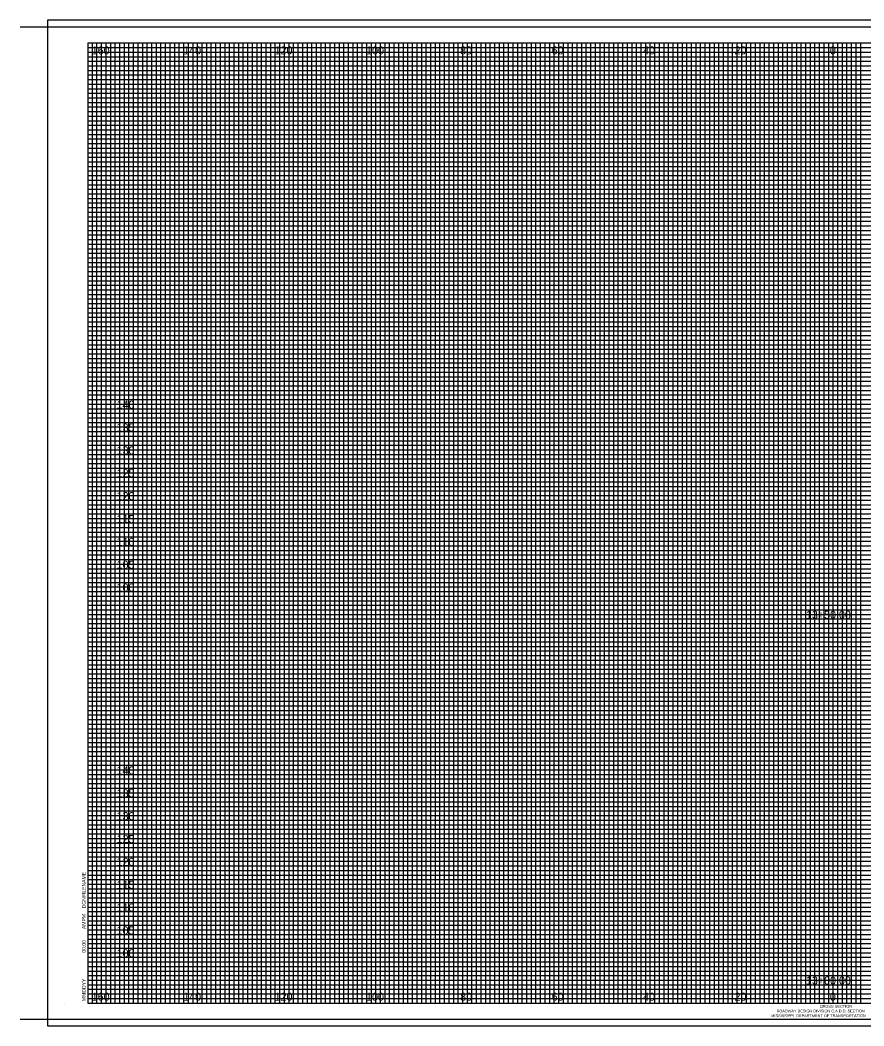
# Model space of a CAD drawing. Extents: x 21281 to 21817, y 6470 to 8300.
# Drawn here: x 21465 to 21649.5, y 7159.8 to 7379.8 of the extents above; entities that cross this region are included whole.
import ezdxf

# ---------------------------------------------------------------- set-up
doc = ezdxf.new("R2010")
doc.units = 0
for name, color, linetype in [('SHEET_BORDER', 7, 'Continuous'), ('SHEET_BORDER_TX', 7, 'Continuous'), ('SHEET_DATE_DGN_TX', 7, 'Continuous'), ('SHEET_PLOTTING_SHAPE', 7, 'Continuous'), ('XS_SHEET_LABELS_ELEVATION', 7, 'Continuous'), ('XS_SHEET_LABELS_OFFSET', 7, 'Continuous'), ('XS_SHEET_LABELS_STATION', 7, 'Continuous'), ('XS_SHEET_MAJOR_GRIDS', 7, 'Continuous'), ('XS_SHEET_MEDIUM_GRIDS', 7, 'Continuous'), ('XS_SHEET_MINOR_GRIDS', 7, 'Continuous')]:
    doc.layers.add(name, color=color, linetype=linetype)

msp = doc.modelspace()

# ---------------------------------------------------------------- linework, layer by layer
at = {"layer": 'SHEET_BORDER'}
for p, q in [((21465.04, 7378.34), (21817.04, 7378.34)), ((21479.84, 7374.84), (21814.84, 7374.84)), ((21479.84, 7374.84), (21479.84, 7164.84)), ((21623.84, 7164.84), (21623.84, 7374.84)), ((21474.84, 7164.84), (21474.84, 7164.84)), ((21479.84, 7164.84), (21814.84, 7164.84)), ((21465.04, 7161.34), (21817.04, 7161.34))]:
    msp.add_line(p, q, dxfattribs=at)
at = {"layer": 'SHEET_PLOTTING_SHAPE'}
msp.add_lwpolyline([(21471.04, 7159.84), (21817.04, 7159.84), (21817.04, 7379.84), (21471.04, 7379.84)], close=True, dxfattribs=at)
at = {"layer": 'XS_SHEET_MAJOR_GRIDS'}
for p, q in [((21484.84, 7164.84), (21484.84, 7374.84)), ((21494.84, 7164.84), (21494.84, 7374.84)), ((21504.84, 7164.84), (21504.84, 7374.84)), ((21514.84, 7164.84), (21514.84, 7374.84)), ((21524.84, 7164.84), (21524.84, 7374.84)), ((21534.84, 7164.84), (21534.84, 7374.84)), ((21544.84, 7164.84), (21544.84, 7374.84)), ((21554.84, 7164.84), (21554.84, 7374.84)), ((21564.84, 7164.84), (21564.84, 7374.84)), ((21574.84, 7164.84), (21574.84, 7374.84)), ((21584.84, 7164.84), (21584.84, 7374.84)), ((21594.84, 7164.84), (21594.84, 7374.84)), ((21604.84, 7164.84), (21604.84, 7374.84)), ((21614.84, 7164.84), (21614.84, 7374.84)), ((21624.84, 7164.84), (21624.84, 7374.84)), ((21634.84, 7164.84), (21634.84, 7374.84)), ((21644.84, 7164.84), (21644.84, 7374.84)), ((21479.84, 7364.84), (21814.84, 7364.84)), ((21479.84, 7354.84), (21814.84, 7354.84)), ((21479.84, 7344.84), (21814.84, 7344.84)), ((21479.84, 7334.84), (21814.84, 7334.84)), ((21479.84, 7324.84), (21814.84, 7324.84)), ((21479.84, 7314.84), (21814.84, 7314.84)), ((21479.84, 7304.84), (21814.84, 7304.84)), ((21479.84, 7294.84), (21814.84, 7294.84)), ((21479.84, 7284.84), (21814.84, 7284.84)), ((21479.84, 7274.84), (21814.84, 7274.84)), ((21479.84, 7264.84), (21814.84, 7264.84)), ((21479.84, 7254.84), (21814.84, 7254.84)), ((21479.84, 7244.84), (21814.84, 7244.84)), ((21479.84, 7234.84), (21814.84, 7234.84)), ((21479.84, 7224.84), (21814.84, 7224.84)), ((21479.84, 7214.84), (21814.84, 7214.84)), ((21479.84, 7204.84), (21814.84, 7204.84)), ((21479.84, 7194.84), (21814.84, 7194.84)), ((21479.84, 7184.84), (21814.84, 7184.84)), ((21479.84, 7174.84), (21814.84, 7174.84))]:
    msp.add_line(p, q, dxfattribs=at)
at = {"layer": 'XS_SHEET_MEDIUM_GRIDS'}
for p, q in [((21489.84, 7164.84), (21489.84, 7374.84)), ((21499.84, 7164.84), (21499.84, 7374.84)), ((21509.84, 7164.84), (21509.84, 7374.84)), ((21519.84, 7164.84), (21519.84, 7374.84)), ((21529.84, 7164.84), (21529.84, 7374.84)), ((21539.84, 7164.84), (21539.84, 7374.84)), ((21549.84, 7164.84), (21549.84, 7374.84)), ((21559.84, 7164.84), (21559.84, 7374.84)), ((21569.84, 7164.84), (21569.84, 7374.84)), ((21579.84, 7164.84), (21579.84, 7374.84)), ((21589.84, 7164.84), (21589.84, 7374.84)), ((21599.84, 7164.84), (21599.84, 7374.84)), ((21609.84, 7164.84), (21609.84, 7374.84)), ((21619.84, 7164.84), (21619.84, 7374.84)), ((21629.84, 7164.84), (21629.84, 7374.84)), ((21639.84, 7164.84), (21639.84, 7374.84)), ((21479.84, 7369.84), (21787.84, 7369.84)), ((21479.84, 7359.84), (21814.84, 7359.84)), ((21479.84, 7349.84), (21814.84, 7349.84)), ((21479.84, 7339.84), (21814.84, 7339.84)), ((21479.84, 7329.84), (21814.84, 7329.84)), ((21479.84, 7319.84), (21814.84, 7319.84)), ((21479.84, 7309.84), (21814.84, 7309.84)), ((21479.84, 7299.84), (21814.84, 7299.84)), ((21479.84, 7289.84), (21814.84, 7289.84)), ((21479.84, 7279.84), (21814.84, 7279.84)), ((21479.84, 7269.84), (21814.84, 7269.84)), ((21479.84, 7259.84), (21814.84, 7259.84)), ((21479.84, 7249.84), (21814.84, 7249.84)), ((21479.84, 7239.84), (21814.84, 7239.84)), ((21479.84, 7229.84), (21814.84, 7229.84)), ((21479.84, 7219.84), (21814.84, 7219.84)), ((21479.84, 7209.84), (21814.84, 7209.84)), ((21479.84, 7199.84), (21814.84, 7199.84)), ((21479.84, 7189.84), (21814.84, 7189.84)), ((21479.84, 7179.84), (21814.84, 7179.84)), ((21479.84, 7169.84), (21804.84, 7169.84))]:
    msp.add_line(p, q, dxfattribs=at)
at = {"layer": 'XS_SHEET_MINOR_GRIDS'}
for p, q in [((21480.84, 7164.84), (21480.84, 7374.84)), ((21481.84, 7164.84), (21481.84, 7374.84)), ((21482.84, 7164.84), (21482.84, 7374.84)), ((21483.84, 7164.84), (21483.84, 7374.84)), ((21485.84, 7164.84), (21485.84, 7374.84)), ((21486.84, 7164.84), (21486.84, 7374.84)), ((21487.84, 7164.84), (21487.84, 7374.84)), ((21488.84, 7164.84), (21488.84, 7374.84)), ((21490.84, 7164.84), (21490.84, 7374.84)), ((21491.84, 7164.84), (21491.84, 7374.84)), ((21492.84, 7164.84), (21492.84, 7374.84)), ((21493.84, 7164.84), (21493.84, 7374.84)), ((21495.84, 7164.84), (21495.84, 7374.84)), ((21496.84, 7164.84), (21496.84, 7374.84)), ((21497.84, 7164.84), (21497.84, 7374.84)), ((21498.84, 7164.84), (21498.84, 7374.84)), ((21500.84, 7164.84), (21500.84, 7374.84)), ((21501.84, 7164.84), (21501.84, 7374.84)), ((21502.84, 7164.84), (21502.84, 7374.84)), ((21503.84, 7164.84), (21503.84, 7374.84)), ((21505.84, 7164.84), (21505.84, 7374.84)), ((21506.84, 7164.84), (21506.84, 7374.84)), ((21507.84, 7164.84), (21507.84, 7374.84)), ((21508.84, 7164.84), (21508.84, 7374.84)), ((21510.84, 7164.84), (21510.84, 7374.84)), ((21511.84, 7164.84), (21511.84, 7374.84)), ((21512.84, 7164.84), (21512.84, 7374.84)), ((21513.84, 7164.84), (21513.84, 7374.84)), ((21515.84, 7164.84), (21515.84, 7374.84)), ((21516.84, 7164.84), (21516.84, 7374.84)), ((21517.84, 7164.84), (21517.84, 7374.84)), ((21518.84, 7164.84), (21518.84, 7374.84)), ((21520.84, 7164.84), (21520.84, 7374.84)), ((21521.84, 7164.84), (21521.84, 7374.84)), ((21522.84, 7164.84), (21522.84, 7374.84)), ((21523.84, 7164.84), (21523.84, 7374.84)), ((21525.84, 7164.84), (21525.84, 7374.84)), ((21526.84, 7164.84), (21526.84, 7374.84)), ((21527.84, 7164.84), (21527.84, 7374.84)), ((21528.84, 7164.84), (21528.84, 7374.84)), ((21530.84, 7164.84), (21530.84, 7374.84)), ((21531.84, 7164.84), (21531.84, 7374.84)), ((21532.84, 7164.84), (21532.84, 7374.84)), ((21533.84, 7164.84), (21533.84, 7374.84)), ((21535.84, 7164.84), (21535.84, 7374.84)), ((21536.84, 7164.84), (21536.84, 7374.84)), ((21537.84, 7164.84), (21537.84, 7374.84)), ((21538.84, 7164.84), (21538.84, 7374.84)), ((21540.84, 7164.84), (21540.84, 7374.84)), ((21541.84, 7164.84), (21541.84, 7374.84)), ((21542.84, 7164.84), (21542.84, 7374.84)), ((21543.84, 7164.84), (21543.84, 7374.84)), ((21545.84, 7164.84), (21545.84, 7374.84)), ((21546.84, 7164.84), (21546.84, 7374.84)), ((21547.84, 7164.84), (21547.84, 7374.84)), ((21548.84, 7164.84), (21548.84, 7374.84)), ((21550.84, 7164.84), (21550.84, 7374.84)), ((21551.84, 7164.84), (21551.84, 7374.84)), ((21552.84, 7164.84), (21552.84, 7374.84)), ((21553.84, 7164.84), (21553.84, 7374.84)), ((21555.84, 7164.84), (21555.84, 7374.84)), ((21556.84, 7164.84), (21556.84, 7374.84)), ((21557.84, 7164.84), (21557.84, 7374.84)), ((21558.84, 7164.84), (21558.84, 7374.84)), ((21560.84, 7164.84), (21560.84, 7374.84)), ((21561.84, 7164.84), (21561.84, 7374.84)), ((21562.84, 7164.84), (21562.84, 7374.84)), ((21563.84, 7164.84), (21563.84, 7374.84)), ((21565.84, 7164.84), (21565.84, 7374.84)), ((21566.84, 7164.84), (21566.84, 7374.84)), ((21567.84, 7164.84), (21567.84, 7374.84)), ((21568.84, 7164.84), (21568.84, 7374.84)), ((21570.84, 7164.84), (21570.84, 7374.84)), ((21571.84, 7164.84), (21571.84, 7374.84)), ((21572.84, 7164.84), (21572.84, 7374.84)), ((21573.84, 7164.84), (21573.84, 7374.84)), ((21575.84, 7164.84), (21575.84, 7374.84)), ((21576.84, 7164.84), (21576.84, 7374.84)), ((21577.84, 7164.84), (21577.84, 7374.84)), ((21578.84, 7164.84), (21578.84, 7374.84)), ((21580.84, 7164.84), (21580.84, 7374.84)), ((21581.84, 7164.84), (21581.84, 7374.84)), ((21582.84, 7164.84), (21582.84, 7374.84)), ((21583.84, 7164.84), (21583.84, 7374.84)), ((21585.84, 7164.84), (21585.84, 7374.84)), ((21586.84, 7164.84), (21586.84, 7374.84)), ((21587.84, 7164.84), (21587.84, 7374.84)), ((21588.84, 7164.84), (21588.84, 7374.84)), ((21590.84, 7164.84), (21590.84, 7374.84)), ((21591.84, 7164.84), (21591.84, 7374.84)), ((21592.84, 7164.84), (21592.84, 7374.84)), ((21593.84, 7164.84), (21593.84, 7374.84)), ((21595.84, 7164.84), (21595.84, 7374.84)), ((21596.84, 7164.84), (21596.84, 7374.84)), ((21597.84, 7164.84), (21597.84, 7374.84)), ((21598.84, 7164.84), (21598.84, 7374.84)), ((21600.84, 7164.84), (21600.84, 7374.84)), ((21601.84, 7164.84), (21601.84, 7374.84)), ((21602.84, 7164.84), (21602.84, 7374.84)), ((21603.84, 7164.84), (21603.84, 7374.84)), ((21605.84, 7164.84), (21605.84, 7374.84)), ((21606.84, 7164.84), (21606.84, 7374.84)), ((21607.84, 7164.84), (21607.84, 7374.84)), ((21608.84, 7164.84), (21608.84, 7374.84)), ((21610.84, 7164.84), (21610.84, 7374.84)), ((21611.84, 7164.84), (21611.84, 7374.84)), ((21612.84, 7164.84), (21612.84, 7374.84)), ((21613.84, 7164.84), (21613.84, 7374.84)), ((21615.84, 7164.84), (21615.84, 7374.84)), ((21616.84, 7164.84), (21616.84, 7374.84)), ((21617.84, 7164.84), (21617.84, 7374.84)), ((21618.84, 7164.84), (21618.84, 7374.84)), ((21620.84, 7164.84), (21620.84, 7374.84)), ((21621.84, 7164.84), (21621.84, 7374.84)), ((21622.84, 7164.84), (21622.84, 7374.84)), ((21625.84, 7164.84), (21625.84, 7374.84)), ((21626.84, 7164.84), (21626.84, 7374.84)), ((21627.84, 7164.84), (21627.84, 7374.84)), ((21628.84, 7164.84), (21628.84, 7374.84)), ((21630.84, 7164.84), (21630.84, 7374.84)), ((21631.84, 7164.84), (21631.84, 7374.84)), ((21632.84, 7164.84), (21632.84, 7374.84)), ((21633.84, 7164.84), (21633.84, 7374.84)), ((21635.84, 7164.84), (21635.84, 7374.84)), ((21636.84, 7164.84), (21636.84, 7374.84)), ((21637.84, 7164.84), (21637.84, 7374.84)), ((21638.84, 7164.84), (21638.84, 7374.84)), ((21640.84, 7164.84), (21640.84, 7374.84)), ((21641.84, 7164.84), (21641.84, 7374.84)), ((21642.84, 7164.84), (21642.84, 7374.84)), ((21643.84, 7164.84), (21643.84, 7374.84)), ((21645.84, 7164.84), (21645.84, 7374.84)), ((21646.84, 7164.84), (21646.84, 7374.84)), ((21647.84, 7164.84), (21647.84, 7374.84)), ((21648.84, 7164.84), (21648.84, 7374.84)), ((21479.84, 7373.84), (21787.84, 7373.84)), ((21479.84, 7372.84), (21787.84, 7372.84)), ((21479.84, 7371.84), (21787.84, 7371.84)), ((21479.84, 7370.84), (21787.84, 7370.84)), ((21479.84, 7368.84), (21787.84, 7368.84)), ((21479.84, 7367.84), (21787.84, 7367.84)), ((21479.84, 7366.84), (21787.84, 7366.84)), ((21479.84, 7365.84), (21814.84, 7365.84)), ((21479.84, 7363.84), (21814.84, 7363.84)), ((21479.84, 7362.84), (21814.84, 7362.84)), ((21479.84, 7361.84), (21814.84, 7361.84)), ((21479.84, 7360.84), (21814.84, 7360.84)), ((21479.84, 7358.84), (21814.84, 7358.84)), ((21479.84, 7357.84), (21814.84, 7357.84)), ((21479.84, 7356.84), (21814.84, 7356.84)), ((21479.84, 7355.84), (21814.84, 7355.84)), ((21479.84, 7353.84), (21814.84, 7353.84)), ((21479.84, 7352.84), (21814.84, 7352.84)), ((21479.84, 7351.84), (21814.84, 7351.84)), ((21479.84, 7350.84), (21814.84, 7350.84)), ((21479.84, 7348.84), (21814.84, 7348.84)), ((21479.84, 7347.84), (21814.84, 7347.84)), ((21479.84, 7346.84), (21814.84, 7346.84)), ((21479.84, 7345.84), (21814.84, 7345.84)), ((21479.84, 7343.84), (21814.84, 7343.84)), ((21479.84, 7342.84), (21814.84, 7342.84)), ((21479.84, 7341.84), (21814.84, 7341.84)), ((21479.84, 7340.84), (21814.84, 7340.84)), ((21479.84, 7338.84), (21814.84, 7338.84)), ((21479.84, 7337.84), (21814.84, 7337.84)), ((21479.84, 7336.84), (21814.84, 7336.84)), ((21479.84, 7335.84), (21814.84, 7335.84)), ((21479.84, 7333.84), (21814.84, 7333.84)), ((21479.84, 7332.84), (21814.84, 7332.84)), ((21479.84, 7331.84), (21814.84, 7331.84)), ((21479.84, 7330.84), (21814.84, 7330.84)), ((21479.84, 7328.84), (21814.84, 7328.84)), ((21479.84, 7327.84), (21814.84, 7327.84)), ((21479.84, 7326.84), (21814.84, 7326.84)), ((21479.84, 7325.84), (21814.84, 7325.84)), ((21479.84, 7323.84), (21814.84, 7323.84)), ((21479.84, 7322.84), (21814.84, 7322.84)), ((21479.84, 7321.84), (21814.84, 7321.84)), ((21479.84, 7320.84), (21814.84, 7320.84)), ((21479.84, 7318.84), (21814.84, 7318.84)), ((21479.84, 7317.84), (21814.84, 7317.84)), ((21479.84, 7316.84), (21814.84, 7316.84)), ((21479.84, 7315.84), (21814.84, 7315.84)), ((21479.84, 7313.84), (21814.84, 7313.84)), ((21479.84, 7312.84), (21814.84, 7312.84)), ((21479.84, 7311.84), (21814.84, 7311.84)), ((21479.84, 7310.84), (21814.84, 7310.84)), ((21479.84, 7308.84), (21814.84, 7308.84)), ((21479.84, 7307.84), (21814.84, 7307.84)), ((21479.84, 7306.84), (21814.84, 7306.84)), ((21479.84, 7305.84), (21814.84, 7305.84)), ((21479.84, 7303.84), (21814.84, 7303.84)), ((21479.84, 7302.84), (21814.84, 7302.84)), ((21479.84, 7301.84), (21814.84, 7301.84)), ((21479.84, 7300.84), (21814.84, 7300.84)), ((21479.84, 7298.84), (21814.84, 7298.84)), ((21479.84, 7297.84), (21814.84, 7297.84)), ((21479.84, 7296.84), (21814.84, 7296.84)), ((21479.84, 7295.84), (21814.84, 7295.84)), ((21479.84, 7293.84), (21814.84, 7293.84)), ((21479.84, 7292.84), (21814.84, 7292.84)), ((21479.84, 7291.84), (21814.84, 7291.84)), ((21479.84, 7290.84), (21814.84, 7290.84)), ((21479.84, 7288.84), (21814.84, 7288.84)), ((21479.84, 7287.84), (21814.84, 7287.84)), ((21479.84, 7286.84), (21814.84, 7286.84)), ((21479.84, 7285.84), (21814.84, 7285.84)), ((21479.84, 7283.84), (21814.84, 7283.84)), ((21479.84, 7282.84), (21814.84, 7282.84)), ((21479.84, 7281.84), (21814.84, 7281.84)), ((21479.84, 7280.84), (21814.84, 7280.84)), ((21479.84, 7278.84), (21814.84, 7278.84)), ((21479.84, 7277.84), (21814.84, 7277.84)), ((21479.84, 7276.84), (21814.84, 7276.84)), ((21479.84, 7275.84), (21814.84, 7275.84)), ((21479.84, 7273.84), (21814.84, 7273.84)), ((21479.84, 7272.84), (21814.84, 7272.84)), ((21479.84, 7271.84), (21814.84, 7271.84)), ((21479.84, 7270.84), (21814.84, 7270.84)), ((21479.84, 7268.84), (21814.84, 7268.84)), ((21479.84, 7267.84), (21814.84, 7267.84)), ((21479.84, 7266.84), (21814.84, 7266.84)), ((21479.84, 7265.84), (21814.84, 7265.84)), ((21479.84, 7263.84), (21814.84, 7263.84)), ((21479.84, 7262.84), (21814.84, 7262.84)), ((21479.84, 7261.84), (21814.84, 7261.84)), ((21479.84, 7260.84), (21814.84, 7260.84)), ((21479.84, 7258.84), (21814.84, 7258.84)), ((21479.84, 7257.84), (21814.84, 7257.84)), ((21479.84, 7256.84), (21814.84, 7256.84)), ((21479.84, 7255.84), (21814.84, 7255.84)), ((21479.84, 7253.84), (21814.84, 7253.84)), ((21479.84, 7252.84), (21814.84, 7252.84)), ((21479.84, 7251.84), (21814.84, 7251.84)), ((21479.84, 7250.84), (21814.84, 7250.84)), ((21479.84, 7248.84), (21814.84, 7248.84)), ((21479.84, 7247.84), (21814.84, 7247.84)), ((21479.84, 7246.84), (21814.84, 7246.84)), ((21479.84, 7245.84), (21814.84, 7245.84)), ((21479.84, 7243.84), (21814.84, 7243.84)), ((21479.84, 7242.84), (21814.84, 7242.84)), ((21479.84, 7241.84), (21814.84, 7241.84)), ((21479.84, 7240.84), (21814.84, 7240.84)), ((21479.84, 7238.84), (21814.84, 7238.84)), ((21479.84, 7237.84), (21814.84, 7237.84)), ((21479.84, 7236.84), (21814.84, 7236.84)), ((21479.84, 7235.84), (21814.84, 7235.84)), ((21479.84, 7233.84), (21814.84, 7233.84)), ((21479.84, 7232.84), (21814.84, 7232.84)), ((21479.84, 7231.84), (21814.84, 7231.84)), ((21479.84, 7230.84), (21814.84, 7230.84)), ((21479.84, 7228.84), (21814.84, 7228.84)), ((21479.84, 7227.84), (21814.84, 7227.84)), ((21479.84, 7226.84), (21814.84, 7226.84)), ((21479.84, 7225.84), (21814.84, 7225.84)), ((21479.84, 7223.84), (21814.84, 7223.84)), ((21479.84, 7222.84), (21814.84, 7222.84)), ((21479.84, 7221.84), (21814.84, 7221.84)), ((21479.84, 7220.84), (21814.84, 7220.84)), ((21479.84, 7218.84), (21814.84, 7218.84)), ((21479.84, 7217.84), (21814.84, 7217.84)), ((21479.84, 7216.84), (21814.84, 7216.84)), ((21479.84, 7215.84), (21814.84, 7215.84)), ((21479.84, 7213.84), (21814.84, 7213.84)), ((21479.84, 7212.84), (21814.84, 7212.84)), ((21479.84, 7211.84), (21814.84, 7211.84)), ((21479.84, 7210.84), (21814.84, 7210.84)), ((21479.84, 7208.84), (21814.84, 7208.84)), ((21479.84, 7207.84), (21814.84, 7207.84)), ((21479.84, 7206.84), (21814.84, 7206.84)), ((21479.84, 7205.84), (21814.84, 7205.84)), ((21479.84, 7203.84), (21814.84, 7203.84)), ((21479.84, 7202.84), (21814.84, 7202.84)), ((21479.84, 7201.84), (21814.84, 7201.84)), ((21479.84, 7200.84), (21814.84, 7200.84)), ((21479.84, 7198.84), (21814.84, 7198.84)), ((21479.84, 7197.84), (21814.84, 7197.84)), ((21479.84, 7196.84), (21814.84, 7196.84)), ((21479.84, 7195.84), (21814.84, 7195.84)), ((21479.84, 7193.84), (21814.84, 7193.84)), ((21479.84, 7192.84), (21814.84, 7192.84)), ((21479.84, 7191.84), (21814.84, 7191.84)), ((21479.84, 7190.84), (21814.84, 7190.84)), ((21479.84, 7188.84), (21814.84, 7188.84)), ((21479.84, 7187.84), (21814.84, 7187.84)), ((21479.84, 7186.84), (21814.84, 7186.84)), ((21479.84, 7185.84), (21814.84, 7185.84)), ((21479.84, 7185.84), (21814.84, 7185.84)), ((21479.84, 7185.84), (21814.84, 7185.84)), ((21479.84, 7183.84), (21814.84, 7183.84)), ((21479.84, 7182.84), (21814.84, 7182.84)), ((21479.84, 7181.84), (21814.84, 7181.84)), ((21479.84, 7180.84), (21814.84, 7180.84)), ((21479.84, 7178.84), (21814.84, 7178.84)), ((21479.84, 7177.84), (21814.84, 7177.84)), ((21479.84, 7176.84), (21814.84, 7176.84)), ((21479.84, 7175.84), (21814.84, 7175.84)), ((21479.84, 7173.84), (21804.84, 7173.84)), ((21479.84, 7172.84), (21804.84, 7172.84)), ((21479.84, 7171.84), (21804.84, 7171.84)), ((21479.84, 7170.84), (21804.84, 7170.84)), ((21479.84, 7170.84), (21804.84, 7170.84)), ((21479.84, 7170.84), (21804.84, 7170.84)), ((21479.84, 7168.84), (21804.84, 7168.84)), ((21479.84, 7167.84), (21804.84, 7167.84)), ((21479.84, 7166.84), (21804.84, 7166.84)), ((21479.84, 7165.84), (21804.84, 7165.84))]:
    msp.add_line(p, q, dxfattribs=at)

# ---------------------------------------------------------------- texts
at = {"layer": 'SHEET_BORDER_TX'}
for s, height, p in [('ROADWAY DESIGN DIVISION C.A.D.D. SECTION', 0.61, (21630.44, 7162.78)), ('CROSS SECTION', 0.62, (21639.87, 7163.81)), ('MISSISSIPPI  DEPARTMENT OF TRANSPORTATION', 0.61, (21629.27, 7161.75))]:
    msp.add_text(s, height=height, dxfattribs=at).set_placement(p)
at = {"layer": 'SHEET_DATE_DGN_TX'}
for s, p in [('DGNFILENAME', (21479.37, 7185.54)), ('AMPM', (21479.37, 7181.02)), ('00:00', (21479.37, 7175.84)), ('MMDDYY', (21479.37, 7165.26))]:
    msp.add_text(s, height=0.8, rotation=90, dxfattribs=at).set_placement(p)
at = {"layer": 'XS_SHEET_LABELS_ELEVATION'}
for s, p in [('  140  ', (21484.84, 7294.84)), ('  135  ', (21484.84, 7289.84)), ('  130  ', (21484.84, 7284.84)), ('  125  ', (21484.84, 7279.84)), ('  120  ', (21484.84, 7274.84)), ('  115  ', (21484.84, 7269.84)), ('  110  ', (21484.84, 7264.84)), ('  105  ', (21484.84, 7259.84)), ('  100  ', (21484.84, 7254.84)), ('  140  ', (21484.84, 7214.84)), ('  135  ', (21484.84, 7209.84)), ('  130  ', (21484.84, 7204.84)), ('  125  ', (21484.84, 7199.84)), ('  120  ', (21484.84, 7194.84)), ('  115  ', (21484.84, 7189.84)), ('  110  ', (21484.84, 7184.84)), ('  105  ', (21484.84, 7179.84)), ('  100  ', (21484.84, 7174.84))]:
    msp.add_text(s, height=1.75, dxfattribs=at).set_placement(p)
at = {"layer": 'XS_SHEET_LABELS_OFFSET'}
for s, p in [('  160  ', (21479.4, 7372.34)), ('  140  ', (21499.39, 7372.34)), ('  120  ', (21519.39, 7372.34)), ('  100  ', (21539.39, 7372.34)), ('  80  ', (21559.95, 7372.34)), ('  60  ', (21579.97, 7372.34)), ('  40  ', (21599.95, 7372.34)), ('  20  ', (21619.95, 7372.34)), ('  0  ', (21640.81, 7372.34)), ('  0  ', (21640.81, 7372.34)), ('  160  ', (21479.4, 7165.34)), ('  140  ', (21499.39, 7165.34)), ('  120  ', (21519.39, 7165.34)), ('  100  ', (21539.39, 7165.34)), ('  80  ', (21559.95, 7165.34)), ('  60  ', (21579.97, 7165.34)), ('  40  ', (21599.95, 7165.34)), ('  20  ', (21619.95, 7165.34)), ('  0  ', (21640.81, 7165.34)), ('  0  ', (21640.81, 7165.34))]:
    msp.add_text(s, height=1.75, dxfattribs=at).set_placement(p)
at = {"layer": 'XS_SHEET_LABELS_STATION'}
for s, p in [('  13+50.00  ', (21635.57, 7248.89)), ('  13+00.00  ', (21635.57, 7168.89))]:
    msp.add_text(s, height=1.75, dxfattribs=at).set_placement(p)

doc.saveas('drawing.dxf')
